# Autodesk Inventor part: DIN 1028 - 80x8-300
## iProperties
Created: 2006-02
Part Number: DIN 1028 - 80x8-300
Cost Center: 2,83 kg
Material: Stahl, weich, unlegiert
Description: Warmgewalzte gleichschenklinge L-Profile
Document SubType Name: Modeling
Standard: DIN 1028
Designer: E. Rappsilber
Authority: 359875,4 mm^3
Standards Organization: DIN
Language: de-DE
Size Designation: 80x8-300
Categories: <MemberInstance><Categories><Category DisplayName="Profilstahle" InternalName="089c4875-fa83-4c05-b084-43b9cc11f5ed" Mnemonic="GRDR"><CategoryParameter DisplayN
Stock Number: 80x8
SaveDate: 2006-11-14
SaveTime: 13:05
FileName: 80x8-300
GesamtGewicht: 2,83 kg
GesamtVolumen: 359875,4 mm^3
IsCustomPart: 1
Author: E. Rappsilber
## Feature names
1. Extrusion1
2. Rundung1 [Fillet]
3. Rundung2 [Fillet]
4. Bohrung1 [Hole]
5. Rechteckige Anordnung1 [Rectangular Pattern]
